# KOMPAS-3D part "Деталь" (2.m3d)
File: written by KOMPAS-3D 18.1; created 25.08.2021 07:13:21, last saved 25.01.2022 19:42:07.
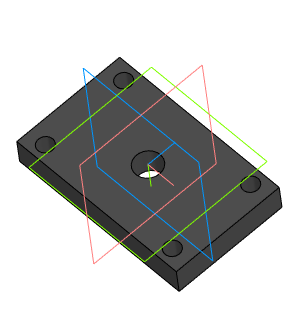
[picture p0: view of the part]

Document properties: Автор: 111; Полное имя файла: C:\Users\admin\Desktop\ffb\2.m3d

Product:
- Part/product: Деталь
    Масса: 0.212612
    source file: 7.cdw

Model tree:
1. Эскиз:1
2. Элемент выдавливания:1
     Расстояние 1 = 10
3. Эскиз:2  (with: Элемент выдавливания:1)
4. Элемент выдавливания:3
     Расстояние 2 = 10
5. Эскиз:3  (with: Элемент выдавливания:1)
6. Элемент выдавливания:4
     Расстояние 2 = 10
